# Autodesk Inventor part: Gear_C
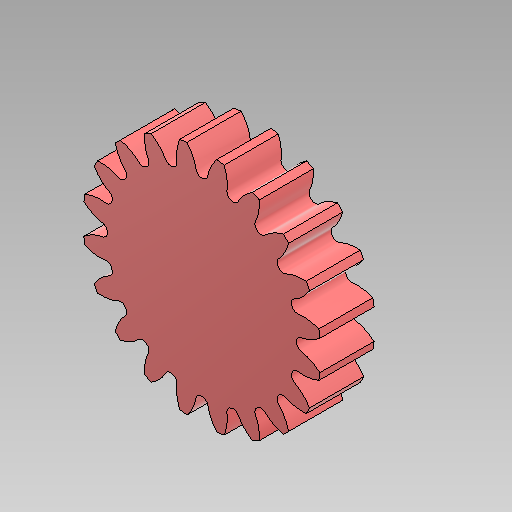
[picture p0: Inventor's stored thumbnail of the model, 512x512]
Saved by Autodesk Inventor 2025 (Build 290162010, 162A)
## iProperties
Created: 2024-10
Part Number: Gear_C
Material: Generic
Document SubType Name: Modeling
Designer: Dennis
Mass: 12.8538 g
Surface Area: 51.6705 cm^2
Volume: 12.8538 cm^3
Density: 1 g/cm^3
Appearance: Smooth - Red
Author: Dennis
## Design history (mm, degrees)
sketch "Sketch1"
  geometry: C1 r 17.5 at (0, 0) reference; C2 r 18.794 at (0, 0) reference; C3 r 20 at (0, 0) reference; A1 r 22 centre (0, 0) between (-2.754, 21.827) and (2.754, 21.827) reference; 54 further points
  constraints: 4 centre point, 2 point on circle, 115 other
extrude "Extrusion1" join sketch "Sketch1" distance "d0" = 10 (= FaceWidth); taper "d1" = 0 deg
extrude "Extrusion2" cut sketch "Sketch1" extent not by distance; stored distance "d2" = 0; taper "d3" = 0 deg
sketch "Sketch2"
  geometry: L1 (-2.754, -10)-(2.754, -10) reference; L2 (0, -10)-(5, -10); L3 (5, -10)-(5, -15); L4 (5, -15)-(2.5, -15); L5 (2.5, -15)-(2.5, -20); L6 (2.5, -20)-(0, -20); L7 (0, -20)-(0, -10); 1 further point
  constraints: 12 end point, 5 perpendicular, 1 horizontal, 1 midpoint, 1 parallel
  dimensions: "d7" = 5 diameter of L5 L7; "d8" = 10 diameter of L3 L7; "d9" = 5 distance of L2.end L3.end
revolve "Revolution1" sketch "Sketch2" stored, may be unused: angle "d10" = 90 deg
body "Solid1"
pattern_circular "Circular Pattern1" dims angle "d5" = 360 deg
other parameters: "Module" = 2 [user parameter], "PressureAngle" = 20 deg [user parameter], "UnitProfileClearance" = 2.5 [user parameter], "UnitRoundRadius" = 3.5 [user parameter], "HeadDiameter" = 44 [user parameter], "RootDiameter" = 35 [user parameter], "BaseDiameter" = 37.5877 [user parameter], "FaceWidth" = 10 [user parameter; used in 1 equation term], "HelixAngle" = 0 [user parameter], "UnitCorrection" = 0 [user parameter], "UnitAddendumModification" = 0 [user parameter], "CircularPitch" = 36 deg [user parameter], "UnitBacklashShift" = 0 [user parameter], "TotalToolShift" = 0 [user parameter], "IsInternal" = 0 [user parameter]
